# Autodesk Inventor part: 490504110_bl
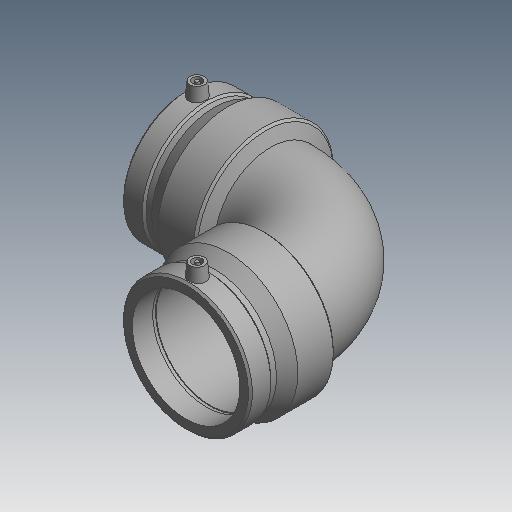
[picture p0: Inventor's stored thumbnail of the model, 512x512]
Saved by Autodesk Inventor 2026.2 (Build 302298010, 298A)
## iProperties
Created: 2017-06
Part Number: 490504110_bl
Material: Generic
Description: PLASSON 90° ELBOW 110
Document SubType Name: Modeling
Designer: KIM
Mass: 55.0731 g
Surface Area: 148.067 cm^2
Volume: 55.0731 cm^3
Density: 1 g/cm^3
Appearance: Default
Author: KIM
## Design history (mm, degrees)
derived "490504.ipt"
feature "Solid1::490504.ipt" dims "ScaleForDerivedMember" = 10
tag "TaggingFeature1"
body "Solid1"
other parameters: "d2" = 143 [user parameter], "d4" = 60.75 [user parameter], "d5" = 128.7 [user parameter], "d8" = 168 deg [user parameter], "d10" = 31.6 [user parameter], "d11" = 10.53333 [user parameter], "d14" = 17.6296 [user parameter], "d19" = 3.52592 [user parameter], "d20" = 168 deg [user parameter], "d22" = 131.56 [user parameter], "d23" = 143 [user parameter], "d24" = 127.6132 [user parameter], "d29" = 79 [user parameter], "d30" = 15 [user parameter], "d31" = 85.05 [user parameter], "d34" = 5 deg [user parameter], "d35" = 15 [user parameter], "d39" = 5 deg [user parameter], "d41" = 4 [user parameter], "d42" = 14 [user parameter], "d43" = 0 [user parameter], "d45" = 4 [user parameter], "d46" = 14 [user parameter], "d47" = 0 [user parameter], "d50" = 93.5 [user parameter], "d51" = 31.6 [user parameter], "d52" = 79 [user parameter], "d54" = 90 deg [user parameter], "d67" = 45 deg [user parameter], "d71" = 90 deg [user parameter], "d75" = 7.15 [user parameter], "d82" = 45 deg [user parameter], "d83" = 79 [user parameter], "d84" = 128.7 [user parameter], "d87" = 90 deg [user parameter], "d90" = 79 [user parameter], "d91" = 0 [user parameter], "d92" = 79 [user parameter], "d93" = 0 [user parameter], "d94" = 90 deg [user parameter], "d101" = 3 [user parameter], "d102" = 0 [user parameter], "d103" = 3 [user parameter], "d104" = 0 [user parameter], "d105" = 22.91 [user parameter], "d106" = 5.7275 [user parameter], "d110" = 43.45 [user parameter], "d111" = 243 [user parameter], "d112" = 243 [user parameter], "d113" = 243 [user parameter], "d114" = 243 [user parameter], "L_" = 243 [user parameter], "L_1" = 79 [user parameter], "D_" = 143 [user parameter], "A_" = 79 [user parameter], "d_2" = 12 [user parameter]
